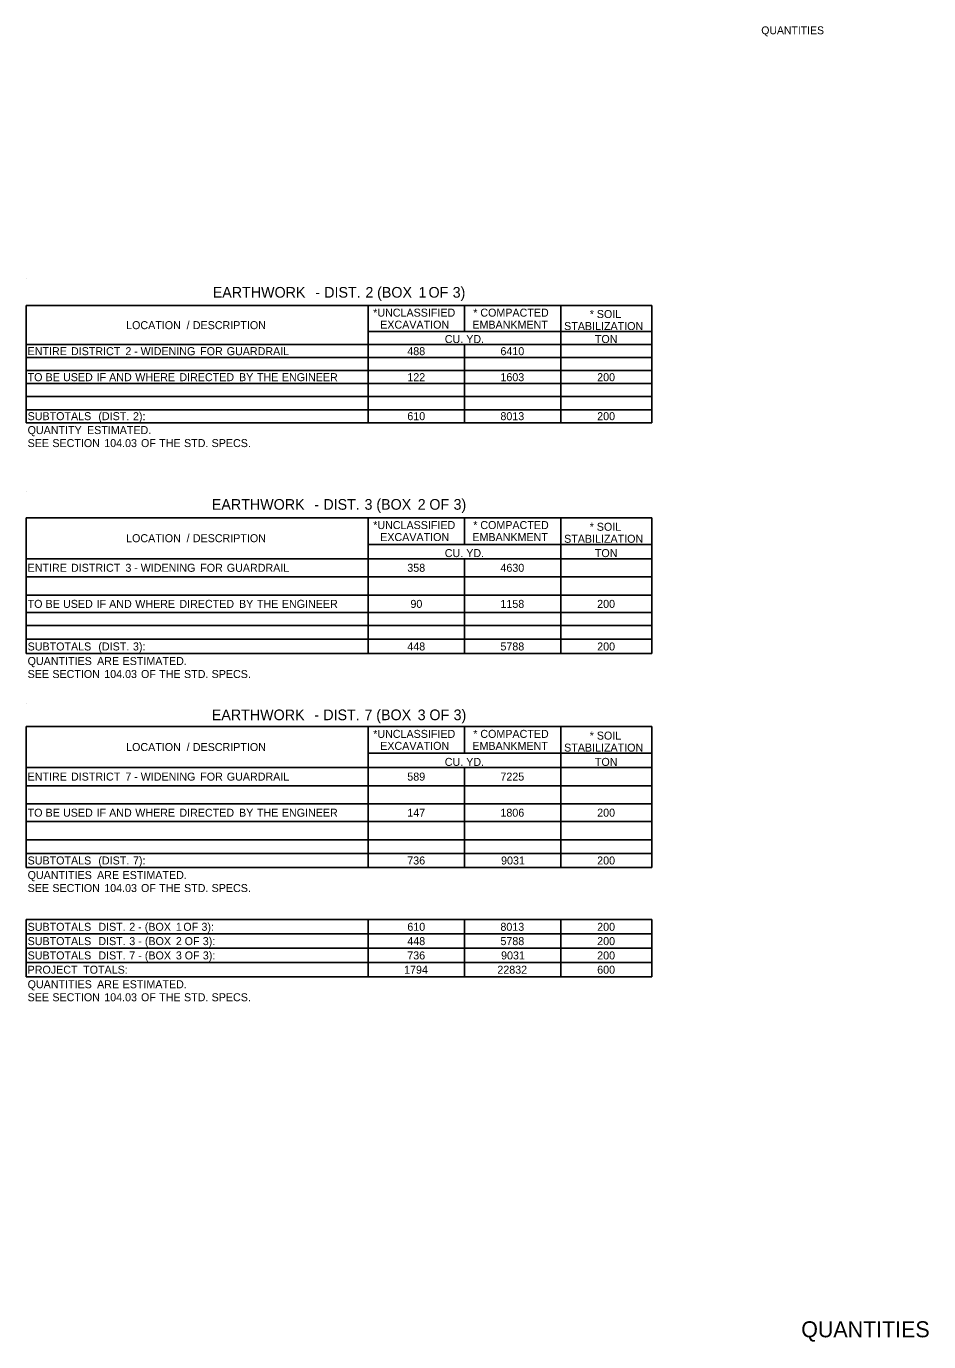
# Model space of a CAD drawing. Extents: x 544250 to 1930787, y -1948365 to 596640.
# Drawn here: x 552712 to 553389, y -1948344 to -1947358 of the extents above; entities that cross this region are included whole.
import ezdxf

# ---------------------------------------------------------------- set-up
doc = ezdxf.new("R2010")
doc.units = 0
for name, color, linetype in [('Default', 7, 'Continuous'), ('R_Border', 7, 'Continuous'), ('R_Border Prem', 7, 'Continuous')]:
    doc.layers.add(name, color=color, linetype=linetype)

msp = doc.modelspace()

# ---------------------------------------------------------------- linework, layer by layer
at = {"layer": 'Default'}
for p, q in [((552712.06, -1947547.41), (552712.06, -1947547.41)), ((552712.06, -1947567.4), (553181.04, -1947567.4)), ((552712.06, -1947655.15), (552712.06, -1947567.4)), ((552968.49, -1947655.15), (552968.49, -1947567.4)), ((553040.64, -1947586.9), (553040.64, -1947567.4)), ((553112.79, -1947655.15), (553112.79, -1947567.4)), ((553181.04, -1947655.15), (553181.04, -1947567.4)), ((552968.49, -1947586.9), (553181.04, -1947586.9)), ((552712.06, -1947596.65), (553181.04, -1947596.65)), ((552968.49, -1947596.65), (553112.79, -1947596.65)), ((553040.64, -1947655.15), (553040.64, -1947596.65)), ((552712.06, -1947606.4), (553181.04, -1947606.4)), ((552712.06, -1947616.15), (553181.04, -1947616.15)), ((552712.06, -1947625.9), (553181.04, -1947625.9)), ((552712.06, -1947635.65), (553181.04, -1947635.65)), ((552712.06, -1947645.4), (553181.04, -1947645.4)), ((552712.06, -1947655.15), (553181.04, -1947655.15)), ((552968.49, -1947645.4), (553112.79, -1947645.4)), ((553112.79, -1947645.4), (553181.04, -1947645.4)), ((552712.06, -1947706.44), (552712.06, -1947706.44)), ((552712.06, -1947726.42), (553181.04, -1947726.42)), ((552712.06, -1947828.31), (552712.06, -1947726.42)), ((552968.49, -1947828.31), (552968.49, -1947726.42)), ((553040.64, -1947746.41), (553040.64, -1947726.42)), ((553112.79, -1947828.31), (553112.79, -1947726.42)), ((553181.04, -1947828.31), (553181.04, -1947726.42)), ((552968.49, -1947746.41), (553181.04, -1947746.41)), ((552712.06, -1947757.14), (553181.04, -1947757.14)), ((552968.49, -1947757.14), (553112.79, -1947757.14)), ((553040.64, -1947828.31), (553040.64, -1947757.14)), ((552712.06, -1947770.79), (553181.04, -1947770.79)), ((552712.06, -1947784.44), (553181.04, -1947784.44)), ((552712.06, -1947797.6), (553181.04, -1947797.6)), ((552712.06, -1947807.35), (553181.04, -1947807.35)), ((552712.06, -1947817.59), (553181.04, -1947817.59)), ((552968.49, -1947817.59), (553112.79, -1947817.59)), ((553112.79, -1947817.59), (553181.04, -1947817.59)), ((552712.06, -1947828.31), (553181.04, -1947828.31)), ((552712.06, -1947865.46), (552712.06, -1947865.46)), ((552712.06, -1947883.01), (553181.04, -1947883.01)), ((552712.06, -1947988.79), (552712.06, -1947883.01)), ((552968.49, -1947988.79), (552968.49, -1947883.01)), ((553040.64, -1947902.99), (553040.64, -1947883.01)), ((553112.79, -1947988.79), (553112.79, -1947883.01)), ((553181.04, -1947988.79), (553181.04, -1947883.01)), ((552968.49, -1947902.99), (553181.04, -1947902.99)), ((552712.06, -1947913.72), (553181.04, -1947913.72)), ((552968.49, -1947913.72), (553112.79, -1947913.72)), ((553040.64, -1947988.79), (553040.64, -1947913.72)), ((552712.06, -1947927.37), (553181.04, -1947927.37)), ((552712.06, -1947941.02), (553181.04, -1947941.02)), ((552712.06, -1947954.18), (553181.04, -1947954.18)), ((552712.06, -1947967.83), (553181.04, -1947967.83)), ((552712.06, -1947978.07), (553181.04, -1947978.07)), ((552968.49, -1947978.07), (553112.79, -1947978.07)), ((553112.79, -1947978.07), (553181.04, -1947978.07)), ((552712.06, -1947988.79), (553181.04, -1947988.79)), ((552712.06, -1948027.79), (553181.04, -1948027.79)), ((552712.06, -1948027.79), (553181.04, -1948027.79)), ((552712.06, -1948070.69), (552712.06, -1948027.79)), ((552968.49, -1948070.69), (552968.49, -1948027.79)), ((553040.64, -1948070.69), (553040.64, -1948027.79)), ((553112.79, -1948070.69), (553112.79, -1948027.79)), ((553181.04, -1948070.69), (553181.04, -1948027.79)), ((552712.06, -1948038.52), (553181.04, -1948038.52)), ((552712.06, -1948049.24), (553181.04, -1948049.24)), ((552712.06, -1948059.97), (553181.04, -1948059.97)), ((552712.06, -1948070.69), (553181.04, -1948070.69))]:
    msp.add_line(p, q, dxfattribs=at)

# ---------------------------------------------------------------- texts
for s, height, p in [('EARTHWORK', 8, (552851.85, -1947561.41)), (' DIST.', 8, (552932.47, -1947561.41)), (' 2', 8, (552963.38, -1947561.41)), (' (BOX', 8, (552972.13, -1947561.41)), (' 1', 8, (553003.17, -1947561.41)), (' OF', 8, (553010.68, -1947561.41)), (' 3)', 8, (553028.79, -1947561.41)), (' -', 8, (552925.73, -1947561.41)), ('*UNCLASSIFIED', 6, (552972.16, -1947575.65)), ('*', 6, (553047.2, -1947575.65)), (' COMPACTED', 6, (553050.28, -1947575.65)), ('*', 6, (553134.55, -1947576.7)), (' SOIL', 6, (553137.63, -1947576.7)), ('LOCATION', 6, (552786.91, -1947585.03)), (' /', 6, (552830.02, -1947585.03)), (' DESCRIPTION', 6, (552834.68, -1947585.03)), ('EXCAVATION', 6, (552977.41, -1947584.65)), ('EMBANKMENT', 6, (553046.52, -1947584.65)), ('STABILIZATION', 6, (553115.34, -1947585.7)), ('CU.', 6, (553025.84, -1947595.45)), (' YD.', 6, (553039.7, -1947595.45)), ('TON', 6, (553138.4, -1947595.45)), ('ENTIRE', 6, (552713.04, -1947604.53)), (' DISTRICT', 6, (552743.33, -1947604.53)), (' 2', 6, (552784.15, -1947604.53)), (' -', 6, (552790.69, -1947604.53)), (' WIDENING', 6, (552795.55, -1947604.53)), (' FOR', 6, (552840.2, -1947604.53)), (' GUARDRAIL', 6, (552860.11, -1947604.53)), ('488', 6, (552997.76, -1947604.53)), ('6410', 6, (553067.59, -1947604.53)), ('TO', 6, (552713.04, -1947624.03)), (' BE', 6, (552724.3, -1947624.03)), (' USED', 6, (552737.37, -1947624.03)), (' IF', 6, (552762.54, -1947624.03)), (' AND', 6, (552771.94, -1947624.03)), (' WHERE', 6, (552791.52, -1947624.03)), (' DIRECTED', 6, (552824.61, -1947624.03)), (' BY', 6, (552869.34, -1947624.03)), (' THE', 6, (552882.79, -1947624.03)), (' ENGINEER', 6, (552901.44, -1947624.03)), ('122', 6, (552997.79, -1947624.03)), ('1603', 6, (553067.58, -1947624.03)), ('200', 6, (553140.12, -1947624.03)), ('SUBTOTALS', 6, (552713.04, -1947653.28)), (' (DIST.', 6, (552763.86, -1947653.28)), (' 2):', 6, (552789.83, -1947653.28)), ('610', 6, (552997.78, -1947653.28)), ('8013', 6, (553067.57, -1947653.28)), ('200', 6, (553140.13, -1947653.28)), ('QUANTITY', 6, (552713.04, -1947663.7)), (' ESTIMATED.', 6, (552755.36, -1947663.7)), ('SEE', 6, (552713.04, -1947673.45)), (' SECTION', 6, (552729.37, -1947673.45)), (' 104.03', 6, (552768.27, -1947673.45)), (' OF', 6, (552795.85, -1947673.45)), (' THE', 6, (552809.44, -1947673.45)), (' STD.', 6, (552828.09, -1947673.45)), (' SPECS.', 6, (552848.78, -1947673.45)), ('EARTHWORK', 8, (552851.19, -1947720.43)), (' DIST.', 8, (552931.81, -1947720.43)), (' 3', 8, (552962.71, -1947720.43)), (' (BOX', 8, (552971.55, -1947720.43)), (' 2', 8, (553002.58, -1947720.43)), (' OF', 8, (553011.34, -1947720.43)), (' 3)', 8, (553029.45, -1947720.43)), (' -', 8, (552925.07, -1947720.43)), ('*UNCLASSIFIED', 6, (552972.16, -1947734.92)), ('*', 6, (553047.2, -1947734.92)), (' COMPACTED', 6, (553050.28, -1947734.92)), ('*', 6, (553134.55, -1947736.21)), (' SOIL', 6, (553137.63, -1947736.21)), ('LOCATION', 6, (552786.91, -1947744.78)), (' /', 6, (552830.02, -1947744.78)), (' DESCRIPTION', 6, (552834.68, -1947744.78)), ('EXCAVATION', 6, (552977.41, -1947743.92)), ('EMBANKMENT', 6, (553046.52, -1947743.92)), ('STABILIZATION', 6, (553115.34, -1947745.21)), ('CU.', 6, (553025.84, -1947755.94)), (' YD.', 6, (553039.7, -1947755.94)), ('TON', 6, (553138.4, -1947755.94)), ('ENTIRE', 6, (552713.04, -1947766.96)), (' DISTRICT', 6, (552743.33, -1947766.96)), (' 3', 6, (552784.15, -1947766.96)), (' WIDENING', 6, (552795.61, -1947766.96)), (' FOR', 6, (552840.26, -1947766.96)), (' GUARDRAIL', 6, (552860.17, -1947766.96)), ('358', 6, (552997.76, -1947766.96)), ('4630', 6, (553067.59, -1947766.96)), (' -', 6, (552790.76, -1947766.96)), ('TO', 6, (552713.04, -1947794.02)), (' BE', 6, (552724.3, -1947794.02)), (' USED', 6, (552737.37, -1947794.02)), (' IF', 6, (552762.54, -1947794.02)), (' AND', 6, (552771.94, -1947794.02)), (' WHERE', 6, (552791.52, -1947794.02)), (' DIRECTED', 6, (552824.61, -1947794.02)), (' BY', 6, (552869.34, -1947794.02)), (' THE', 6, (552882.79, -1947794.02)), (' ENGINEER', 6, (552901.44, -1947794.02)), ('90', 6, (553000.1, -1947794.02)), ('1158', 6, (553067.58, -1947794.02)), ('200', 6, (553140.12, -1947794.02)), ('SUBTOTALS', 6, (552713.04, -1947825.95)), (' (DIST.', 6, (552763.86, -1947825.95)), (' 3):', 6, (552789.83, -1947825.95)), ('448', 6, (552997.76, -1947825.95)), ('5788', 6, (553067.58, -1947825.95)), ('200', 6, (553140.13, -1947825.95)), ('QUANTITIES', 6, (552713.04, -1947836.86)), (' ARE', 6, (552762.91, -1947836.86)), (' ESTIMATED.', 6, (552782.03, -1947836.86)), ('SEE', 6, (552713.04, -1947846.61)), (' SECTION', 6, (552729.37, -1947846.61)), (' 104.03', 6, (552768.27, -1947846.61)), (' OF', 6, (552795.85, -1947846.61)), (' THE', 6, (552809.44, -1947846.61)), (' STD.', 6, (552828.09, -1947846.61)), (' SPECS.', 6, (552848.78, -1947846.61)), ('EARTHWORK', 8, (552851.15, -1947878.23)), (' DIST.', 8, (552931.78, -1947878.23)), (' 7', 8, (552962.68, -1947878.23)), (' (BOX', 8, (552971.5, -1947878.23)), (' 3', 8, (553002.54, -1947878.23)), (' OF', 8, (553011.37, -1947878.23)), (' 3)', 8, (553029.48, -1947878.23)), (' -', 8, (552925.03, -1947878.23)), ('*UNCLASSIFIED', 6, (552972.16, -1947891.5)), ('*', 6, (553047.2, -1947891.5)), (' COMPACTED', 6, (553050.28, -1947891.5)), ('*', 6, (553134.55, -1947892.79)), (' SOIL', 6, (553137.63, -1947892.79)), ('LOCATION', 6, (552786.91, -1947901.36)), (' /', 6, (552830.02, -1947901.36)), (' DESCRIPTION', 6, (552834.68, -1947901.36)), ('EXCAVATION', 6, (552977.41, -1947900.5)), ('EMBANKMENT', 6, (553046.52, -1947900.5)), ('STABILIZATION', 6, (553115.34, -1947901.79)), ('CU.', 6, (553025.84, -1947912.52)), (' YD.', 6, (553039.7, -1947912.52)), ('TON', 6, (553138.4, -1947912.52)), ('ENTIRE', 6, (552713.04, -1947923.54)), (' DISTRICT', 6, (552743.33, -1947923.54)), (' 7', 6, (552784.15, -1947923.54)), (' -', 6, (552790.76, -1947923.54)), (' WIDENING', 6, (552795.61, -1947923.54)), (' FOR', 6, (552840.26, -1947923.54)), (' GUARDRAIL', 6, (552860.17, -1947923.54)), ('589', 6, (552997.76, -1947923.54)), ('7225', 6, (553067.56, -1947923.54)), ('TO', 6, (552713.04, -1947950.6)), (' BE', 6, (552724.3, -1947950.6)), (' USED', 6, (552737.37, -1947950.6)), (' IF', 6, (552762.54, -1947950.6)), (' AND', 6, (552771.94, -1947950.6)), (' WHERE', 6, (552791.52, -1947950.6)), (' DIRECTED', 6, (552824.61, -1947950.6)), (' BY', 6, (552869.34, -1947950.6)), (' THE', 6, (552882.79, -1947950.6)), (' ENGINEER', 6, (552901.44, -1947950.6)), ('147', 6, (552997.76, -1947950.6)), ('1806', 6, (553067.58, -1947950.6)), ('200', 6, (553140.12, -1947950.6)), ('SUBTOTALS', 6, (552713.04, -1947986.43)), (' (DIST.', 6, (552763.86, -1947986.43)), (' 7):', 6, (552789.83, -1947986.43)), ('736', 6, (552997.72, -1947986.43)), ('9031', 6, (553068.07, -1947986.43)), ('200', 6, (553140.13, -1947986.43)), ('QUANTITIES', 6, (552713.04, -1947997.34)), (' ARE', 6, (552762.91, -1947997.34)), (' ESTIMATED.', 6, (552782.03, -1947997.34)), ('SEE', 6, (552713.04, -1948007.09)), (' SECTION', 6, (552729.37, -1948007.09)), (' 104.03', 6, (552768.27, -1948007.09)), (' OF', 6, (552795.85, -1948007.09)), (' THE', 6, (552809.44, -1948007.09)), (' STD.', 6, (552828.09, -1948007.09)), (' SPECS.', 6, (552848.78, -1948007.09)), (' (BOX', 6, (552798.66, -1948036.16)), (' 3):', 6, (552841.15, -1948036.16)), ('SUBTOTALS', 6, (552713.04, -1948036.16)), (' DIST.', 6, (552763.86, -1948036.16)), (' 2', 6, (552787.04, -1948036.16)), (' -', 6, (552793.61, -1948036.16)), (' 1', 6, (552821.94, -1948036.16)), (' OF', 6, (552827.57, -1948036.16)), ('610', 6, (552997.78, -1948036.16)), ('8013', 6, (553067.57, -1948036.16)), ('200', 6, (553140.13, -1948036.16)), ('SUBTOTALS', 6, (552713.04, -1948046.88)), (' DIST.', 6, (552763.86, -1948046.88)), (' 3', 6, (552787.04, -1948046.88)), (' -', 6, (552793.66, -1948046.88)), (' (BOX', 6, (552798.72, -1948046.88)), (' 2', 6, (552822, -1948046.88)), (' OF', 6, (552828.57, -1948046.88)), (' 3):', 6, (552842.15, -1948046.88)), ('448', 6, (552997.76, -1948046.88)), ('5788', 6, (553067.58, -1948046.88)), ('200', 6, (553140.13, -1948046.88)), ('SUBTOTALS', 6, (552713.04, -1948057.61)), (' DIST.', 6, (552763.86, -1948057.61)), (' 7', 6, (552787.04, -1948057.61)), (' -', 6, (552793.66, -1948057.61)), (' (BOX', 6, (552798.71, -1948057.61)), (' 3', 6, (552821.99, -1948057.61)), (' OF', 6, (552828.62, -1948057.61)), (' 3):', 6, (552842.2, -1948057.61)), ('736', 6, (552997.72, -1948057.61)), ('9031', 6, (553068.07, -1948057.61)), ('200', 6, (553140.13, -1948057.61)), ('PROJECT', 6, (552713.04, -1948068.33)), (' TOTALS:', 6, (552752.46, -1948068.33)), ('1794', 6, (552995.34, -1948068.33)), ('22832', 6, (553065.27, -1948068.33)), ('600', 6, (553140.13, -1948068.33)), ('QUANTITIES', 6, (552713.04, -1948079.24)), (' ARE', 6, (552762.91, -1948079.24)), (' ESTIMATED.', 6, (552782.03, -1948079.24)), ('SEE', 6, (552713.04, -1948088.99)), (' SECTION', 6, (552729.37, -1948088.99)), (' 104.03', 6, (552768.27, -1948088.99)), (' OF', 6, (552795.85, -1948088.99)), (' THE', 6, (552809.44, -1948088.99)), (' STD.', 6, (552828.09, -1948088.99)), (' SPECS.', 6, (552848.78, -1948088.99))]:
    msp.add_text(s, height=height, dxfattribs=at).set_placement(p)
at = {"layer": 'R_Border'}
msp.add_text('QUANTITIES', height=12, rotation=360, dxfattribs=at).set_placement((553293.15, -1948340.95))
at = {"layer": 'R_Border Prem'}
msp.add_text('QUANTITIES', height=5.862, rotation=360, dxfattribs=at).set_placement((553263.17, -1947363.9))

doc.saveas('drawing.dxf')
